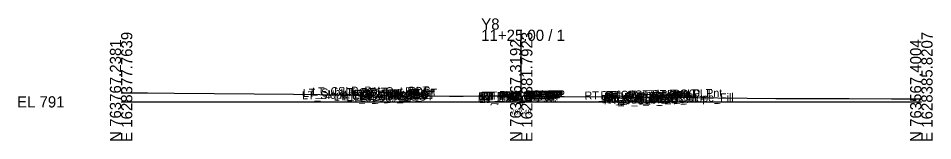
# Model space of a CAD drawing. Extents: x -26 to 203, y -10 to 3017.
# Drawn here: x -25.7 to 202.8, y 2490.3 to 2520.9 of the extents above; entities that cross this region are included whole.
import ezdxf

# ---------------------------------------------------------------- set-up
doc = ezdxf.new("R2010")
doc.units = 0
for name, color, linetype in [('Exist Cross Section Cell', 7, 'Continuous'), ('Exist XS Center Line Elevation Label', 7, 'Continuous'), ('Exist XS Ground Line', 7, 'Continuous'), ('Scratch_Level_0', 7, 'Continuous')]:
    doc.layers.add(name, color=color, linetype=linetype)

msp = doc.modelspace()

# ---------------------------------------------------------------- linework, layer by layer
at = {"layer": 'Exist Cross Section Cell'}
for p, q in [((100, 2500), (100, 2518.03)), ((0, 2500), (100, 2500)), ((100, 2500), (200, 2500))]:
    msp.add_line(p, q, dxfattribs=at)
at = {"layer": 'Exist XS Ground Line'}
msp.add_lwpolyline([(0, 2502.29), (6.58, 2502.22), (13.25, 2502.16), (33.24, 2501.99), (43.12, 2501.9), (56.22, 2501.79), (60.5, 2501.62), (62.1, 2501.53), (82.04, 2501.42), (83.75, 2501.44), (84.7, 2501.43), (85.48, 2501.45), (90.96, 2501.54), (100, 2501.48), (103.89, 2501.46), (108.34, 2501.37), (109.48, 2501.35), (110.73, 2501.35), (130.94, 2501.17), (132.03, 2501.14), (141.73, 2501.06), (156.49, 2500.93), (163.6, 2500.88), (181.93, 2500.81), (192.51, 2500.76), (200, 2500.73)], dxfattribs=at)

# ---------------------------------------------------------------- texts
at = {"layer": 'Exist Cross Section Cell'}
for s, p in [('Y8', (90, 2518.03)), ('11+25.00 / 1', (90, 2515.23)), ('EL 791', (-26, 2498.6))]:
    msp.add_text(s, height=2.8, dxfattribs=at).set_placement(p)
for s, p in [('E 1628377.7639', (2.8, 2490)), ('E 1628381.7923', (102.8, 2490)), ('E 1628385.8207', (202.8, 2490)), ('N 763767.2381', (0, 2490)), ('N 763667.3192', (100, 2490)), ('N 763567.4004', (200, 2490))]:
    msp.add_text(s, height=2.8, rotation=90, dxfattribs=at).set_placement(p)
at = {"layer": 'Exist XS Center Line Elevation Label'}
msp.add_text('792.48', height=1.2, dxfattribs=at).set_placement((97.46, 2496.88))
at = {"layer": 'Scratch_Level_0'}
for s, p in [('LT_Slope_Fill', (45.22, 2500.61)), ('LT_Sub_Trench_Out_DLT', (45.45, 2501.23)), ('LT_CSLP_Pnt', (47.75, 2501.56)), ('LT_CG1_Shelf_Out', (53.13, 2500.31)), ('LT_CG_Top_Face', (54.83, 2501.32)), ('LT_CG_Top_BOC', (55.36, 2501.34)), ('LT_CG_Bot_BOC', (55.39, 2500.34)), ('LT_CG_Top_Gut', (55.81, 2500.83)), ('LT_CG_Bot_IE', (59.49, 2500.34)), ('LT_PV2_OEOT', (59.75, 2500.68)), ('LT_PV3_OEOT', (59.75, 2500.35)), ('LT_PV1_OEOT', (60.31, 2500.94)), ('RT_PV2_OEEOP', (89.28, 2500.36)), ('RT_PV3_OEEOP', (89.28, 2500.03)), ('LT_PV2_OEEOP', (89.33, 2500.36)), ('RT_PV1_OEEOP', (89.85, 2500.5)), ('LT_PV1_OEEOP', (89.9, 2500.5)), ('RT_PV2_IEEOP', (89.93, 2500.37)), ('LT_PV2_IEEOP', (89.97, 2500.37)), ('RT_PV1_IEEOP', (90.49, 2500.51)), ('LT_PV1_IEEOP', (90.54, 2500.51)), ('PV2_PGL', (93.93, 2500.45)), ('PV1_PGL', (94.49, 2500.71)), ('RT_Sub_Trench_Out_DLT', (115.85, 2500.57)), ('RT_CG_Top_Face', (119.82, 2500.66)), ('RT_PV2_OEOT', (120.73, 2500.07)), ('RT_CG_Top_Gut', (120.79, 2500.18)), ('RT_PV1_OEOT', (121.29, 2500.33)), ('RT_CG_Top_BOC', (121.34, 2500.68)), ('RT_CSLP_Pnt', (132.73, 2500.91)), ('LT_Sub_OEOP', (56.35, 2500.05)), ('LT_Sub_OEOT', (59.65, 2500.01)), ('RT_Sub_OEEOP', (89.19, 2499.69)), ('LT_Sub_OEEOP', (89.23, 2499.69)), ('LT_PV3_OEEOP', (89.33, 2500.03)), ('RT_CG1_Shelf_Out', (120.11, 2499.64)), ('RT_CG_Bot_IE', (120.47, 2499.73)), ('RT_Sub_OEOT', (120.63, 2499.4)), ('RT_PV3_OEOT', (120.73, 2499.74)), ('RT_CG_Bot_BOC', (121.37, 2499.68)), ('RT_Sub_OEOP', (124, 2499.37)), ('RT_Slope_Fill', (136.34, 2499.83))]:
    msp.add_text(s, height=2, rotation=1.1458, dxfattribs=at).set_placement(p)

doc.saveas('drawing.dxf')
